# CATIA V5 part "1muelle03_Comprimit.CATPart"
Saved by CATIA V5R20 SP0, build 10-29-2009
Part number: 1muelle03_Comprimit
Revision: ANY
Definition: UNKNOWN
Nomenclature: 1muelle03_Comprimit
Source: Unknown
Bounding box of the stored display mesh (mm): x -3.4 to 3.4, y -3.4 to 3.4, z -0.001 to 8.149
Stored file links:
  C:\Users\Utente\Desktop\IO LAVORO\3D X SITO CF\CUMSA\3D files AE\AE 031620\1muelle03_Comprimit.CATPart
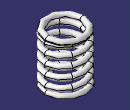
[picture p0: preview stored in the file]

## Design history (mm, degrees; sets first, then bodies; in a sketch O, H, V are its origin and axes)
Set1 "FacciaKO#NONE#13977"
  DatumSurface1 "Sup13977_1"
  DatumCurve1 "Crv13977_1"
Set2 "FacciaKO#NONE#10031"
  DatumSurface2 "Sup10031_1"
  DatumCurve2 "Crv10031_1"
Body1 "Cortar-Extruir2" (main body)
  Solid1: solid without history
